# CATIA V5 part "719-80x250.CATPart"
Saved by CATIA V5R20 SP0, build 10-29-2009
Part number: 719-80x250
Definition: NONE
Nomenclature: 719-80x250
Source: Unknown
Description: 719-80x250
Bounding box of the stored display mesh (mm): x 0 to 310, y -47.5 to 47.5, z -47.5 to 47.5
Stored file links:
  C:\Users\Utente\Desktop\IO LAVORO\3D X SITO CF\X SITO\719\719-80x250.CATPart
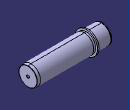
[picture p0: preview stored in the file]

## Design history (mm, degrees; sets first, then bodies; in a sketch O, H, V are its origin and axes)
Body1 "719-80x250" (main body)
  Solid1: solid without history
